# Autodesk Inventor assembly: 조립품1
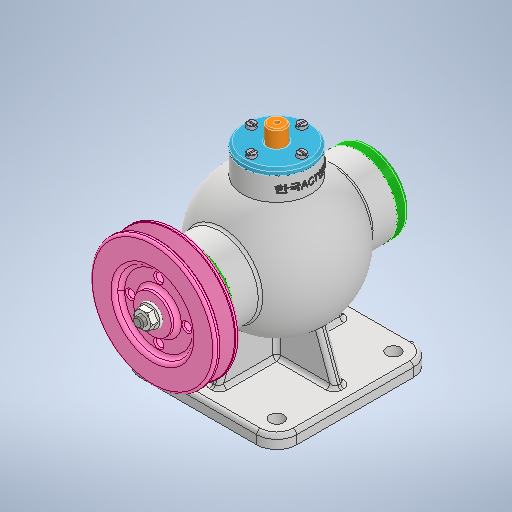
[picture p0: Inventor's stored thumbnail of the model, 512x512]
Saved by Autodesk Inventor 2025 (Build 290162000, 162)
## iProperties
Created: 2024-07
Part Number: 조립품1
Document SubType Name: Assembly
Designer: samsung
Author: samsung
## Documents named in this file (15)
- C:\Users\samsung\Desktop\740708V1012\조립품1.iam
- C:\Users\samsung\Desktop\740708V1012\본체1.ipt
- C:\Users\samsung\Desktop\740708V1012\베어링- 6202\베어링- 6202.ipt
- C:\Users\samsung\Desktop\740708V1012\뒤커버\뒤커버.ipt
- C:\Users\samsung\Desktop\740708V1012\칼라\칼라.ipt
- C:\Users\samsung\Desktop\740708V1012\편심축\편심축.ipt
- C:\Users\samsung\Desktop\740708V1012\앞커버\앞커버.ipt
- C:\Users\samsung\Desktop\740708V1012\키 4 x 4 x 12\키 4 x 4 x 12.ipt
- C:\Users\samsung\Desktop\740708V1012\V-벨트풀리\V-벨트풀리.ipt
- C:\Users\samsung\Desktop\740708V1012\너트 M8\너트 M8.ipt
- C:\Users\samsung\Desktop\740708V1012\슬라이드\슬라이드.ipt
- C:\Users\samsung\Desktop\740708V1012\상부커버\상부커버.ipt
- C:\Users\samsung\Desktop\740708V1012\볼트 M4 x 16\볼트 M4 x 16.ipt
- C:\Users\samsung\Desktop\740708V1012\볼트 M4 x 12\볼트 M4 x 12.ipt
- C:\Users\samsung\Desktop\740708V1012\오일실 15 30 7\오일실 15 30 7.ipt
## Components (1 placed, 1 different names)
1. V-벨트풀리:1 — 각도:3
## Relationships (1: Angle 1)
- 각도:3 [Angle]: V-벨트풀리:1
